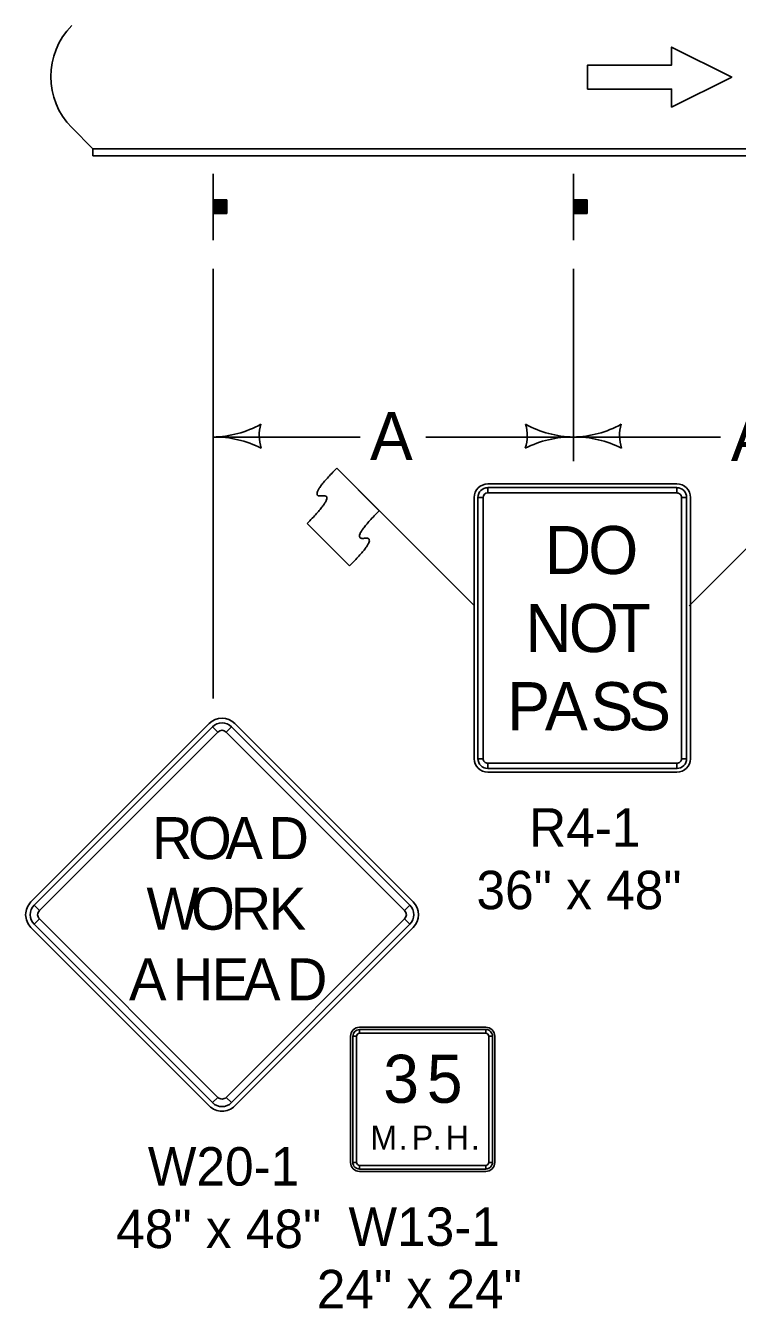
# Model space of a CAD drawing. Extents: x 10133 to 81668, y 4692 to 11018.
# Drawn here: x 20955 to 21251, y 6322 to 6856 of the extents above; entities that cross this region are included whole.
import ezdxf

# ---------------------------------------------------------------- set-up
doc = ezdxf.new("R2010")
doc.units = 0
for name, color, linetype in [('dsnCellElements', 7, 'Continuous'), ('dsnTextTabulation', 7, 'Continuous'), ('Level 5', 7, 'Continuous'), ('SheetAddendum', 7, 'Continuous')]:
    doc.layers.add(name, color=color, linetype=linetype)

msp = doc.modelspace()

# ---------------------------------------------------------------- linework, layer by layer
at = {"layer": 'dsnCellElements'}
for p, q in [((20982.53, 6804.8), (20973.74, 6813.59)), ((20973.74, 6813.59), (20982.53, 6804.8)), ((20982.53, 6801.8), (20982.53, 6804.8)), ((20982.53, 6804.8), (22482.53, 6804.8)), ((21032.53, 6794.3), (21032.53, 6766.8)), ((21182.53, 6794.3), (21182.53, 6766.8)), ((21032.94, 6777.86), (21032.94, 6783.44)), ((21033.22, 6783.44), (21033.22, 6777.86)), ((21033.48, 6777.86), (21033.48, 6783.44)), ((21033.75, 6783.44), (21033.75, 6777.86)), ((21033.97, 6777.86), (21033.97, 6783.44)), ((21034.18, 6783.44), (21034.18, 6777.86)), ((21034.52, 6777.86), (21034.52, 6783.44)), ((21034.78, 6783.44), (21034.78, 6777.86)), ((21035, 6777.86), (21034.98, 6783.44)), ((21035.32, 6783.44), (21035.32, 6777.86)), ((21035.7, 6777.86), (21035.7, 6783.44)), ((21036.13, 6783.44), (21036.13, 6777.86)), ((21036.35, 6777.86), (21036.33, 6783.44)), ((21036.77, 6783.44), (21036.78, 6777.86)), ((21036.99, 6777.86), (21036.99, 6783.44)), ((21037.31, 6783.44), (21037.31, 6777.86)), ((21037.53, 6777.86), (21037.53, 6783.44)), ((21037.85, 6783.44), (21037.85, 6777.86)), ((21182.94, 6777.86), (21182.94, 6783.44)), ((21183.22, 6783.44), (21183.22, 6777.86)), ((21183.48, 6777.86), (21183.48, 6783.44)), ((21183.75, 6783.44), (21183.75, 6777.86)), ((21183.97, 6777.86), (21183.97, 6783.44)), ((21184.18, 6783.44), (21184.18, 6777.86)), ((21184.52, 6777.86), (21184.52, 6783.44)), ((21184.78, 6783.44), (21184.78, 6777.86)), ((21185, 6777.86), (21184.98, 6783.44)), ((21185.32, 6783.44), (21185.32, 6777.86)), ((21185.7, 6777.86), (21185.7, 6783.44)), ((21186.13, 6783.44), (21186.13, 6777.86)), ((21186.35, 6777.86), (21186.33, 6783.44)), ((21186.77, 6783.44), (21186.78, 6777.86)), ((21186.99, 6777.86), (21186.99, 6783.44)), ((21187.31, 6783.44), (21187.31, 6777.86)), ((21187.53, 6777.86), (21187.53, 6783.44)), ((21187.85, 6783.44), (21187.85, 6777.86)), ((21032.53, 6575.99), (21032.53, 6754.8)), ((21182.53, 6674.8), (21182.53, 6754.8)), ((21032.53, 6684.8), (21093.7, 6684.8)), ((21121.03, 6684.8), (21182.53, 6684.8)), ((21182.53, 6684.8), (21243.7, 6684.8))]:
    msp.add_line(p, q, dxfattribs=at)
for points in [[(21188.42, 6839.63), (21188.42, 6829.63), (21223.42, 6829.63), (21223.42, 6822.13), (21248.42, 6834.63), (21223.42, 6847.13), (21223.42, 6839.63)], [(21032.62, 6777.86), (21032.62, 6783.48), (21038.25, 6783.48), (21038.25, 6777.86)], [(21182.62, 6777.86), (21182.62, 6783.48), (21188.25, 6783.48), (21188.25, 6777.86)]]:
    msp.add_lwpolyline(points, close=True, dxfattribs=at)
msp.add_lwpolyline([(21223.42, 6839.63), (21223.42, 6847.13), (21248.42, 6834.63), (21223.42, 6822.13), (21223.42, 6829.63), (21188.42, 6829.63), (21188.42, 6839.63), (21223.42, 6839.63)], dxfattribs=at)
for centre, radius, start, end in [((20994.95, 6834.8), 30, 135, 225), ((20994.95, 6834.8), 30, 135, 225), ((21031.77, 6727.3), 42.5, 271.0176, 299.0725), ((21068.14, 6685.43), 16.42, 163.2666, 198.7334), ((21146.91, 6685.43), 16.42, 341.2666, 16.7334), ((21183.28, 6727.3), 42.5, 240.9275, 268.9824), ((21181.77, 6727.3), 42.5, 271.0176, 299.0725), ((21218.14, 6685.43), 16.42, 163.2666, 198.7334), ((21033.26, 6642.31), 42.5, 62.9275, 90.9824), ((21181.8, 6642.31), 42.5, 89.0176, 117.0725), ((21183.26, 6642.31), 42.5, 62.9275, 90.9824)]:
    msp.add_arc(centre, radius, start, end, dxfattribs=at)
at = {"layer": 'dsnTextTabulation'}
for p, q in [((20982.53, 6804.8), (22482.53, 6804.8)), ((20982.53, 6804.8), (22482.53, 6804.8)), ((21627.53, 6804.8), (20982.53, 6804.8)), ((20982.53, 6804.8), (20982.53, 6801.8)), ((20982.53, 6801.8), (22482.53, 6801.8)), ((20982.53, 6801.8), (22482.53, 6801.8))]:
    msp.add_line(p, q, dxfattribs=at)
at = {"layer": 'Level 5'}
msp.add_line((21071.66, 6648.85), (21089.34, 6631.17), dxfattribs=at)
for points in [[(21084.03, 6671.84), (21071.66, 6659.45), (21084.03, 6661.22), (21071.66, 6648.85)], [(21101.72, 6654.16), (21089.34, 6641.78), (21101.71, 6643.55), (21089.34, 6631.17)]]:
    msp.add_open_spline(points, degree=2, dxfattribs=at)
at = {"layer": 'SheetAddendum'}
for p, q in [((21141.37, 6614.54), (21084.03, 6671.84)), ((21084.03, 6671.84), (21101.72, 6654.16)), ((21230.66, 6614.54), (21287.98, 6671.86)), ((21225.61, 6665.3), (21146.86, 6665.3)), ((21146.86, 6661.55), (21146.86, 6663.74)), ((21225.61, 6663.74), (21225.61, 6661.55)), ((21141.23, 6659.67), (21141.23, 6550.92)), ((21142.8, 6659.67), (21144.98, 6659.67)), ((21227.48, 6659.67), (21229.67, 6659.67)), ((21231.23, 6550.92), (21231.23, 6659.67)), ((21089.34, 6631.17), (21071.66, 6648.85)), ((21030.95, 6565.57), (20956.7, 6491.32)), ((21032.27, 6564.24), (21034.48, 6562.03)), ((21038.02, 6562.03), (21040.23, 6564.24)), ((21115.8, 6491.32), (21041.55, 6565.57)), ((21144.98, 6550.92), (21142.8, 6550.92)), ((21229.67, 6550.92), (21227.48, 6550.92)), ((21146.86, 6546.86), (21146.86, 6549.05)), ((21146.86, 6545.3), (21225.61, 6545.3)), ((21225.61, 6549.05), (21225.61, 6546.86)), ((20960.24, 6487.78), (20958.03, 6489.99)), ((21114.47, 6489.99), (21112.27, 6487.78)), ((20956.7, 6480.71), (21030.95, 6406.47)), ((20958.03, 6482.04), (20960.24, 6484.25)), ((21041.55, 6406.47), (21115.8, 6480.71)), ((21112.27, 6484.25), (21114.47, 6482.04)), ((21146.02, 6439.19), (21093.52, 6439.19)), ((21093.52, 6436.69), (21093.52, 6438.25)), ((21146.02, 6438.25), (21146.02, 6436.69)), ((21089.77, 6435.44), (21089.77, 6382.94)), ((21090.71, 6435.44), (21092.27, 6435.44)), ((21147.27, 6435.44), (21148.83, 6435.44)), ((21149.77, 6382.94), (21149.77, 6435.44)), ((21034.48, 6410), (21032.27, 6407.79)), ((21040.23, 6407.79), (21038.02, 6410)), ((21092.27, 6382.94), (21090.71, 6382.94)), ((21093.52, 6380.13), (21093.52, 6381.69)), ((21146.02, 6381.69), (21146.02, 6380.13)), ((21148.83, 6382.94), (21147.27, 6382.94)), ((21093.52, 6379.19), (21146.02, 6379.19))]:
    msp.add_line(p, q, dxfattribs=at)
for points in [[(21225.61, 6663.74), (21146.86, 6663.74), (21146.86, 6661.55), (21225.61, 6661.55), (21225.61, 6663.74)], [(21142.8, 6659.67), (21142.8, 6550.92), (21144.98, 6550.92), (21144.98, 6659.67), (21142.8, 6659.67)], [(21229.67, 6550.92), (21229.67, 6659.67), (21227.48, 6659.67), (21227.48, 6550.92), (21229.67, 6550.92)], [(21032.27, 6564.24), (20958.03, 6489.99), (20960.24, 6487.78), (21034.48, 6562.03), (21032.27, 6564.24)], [(21114.47, 6489.99), (21040.23, 6564.24), (21038.02, 6562.03), (21112.27, 6487.78), (21114.47, 6489.99)], [(21146.86, 6546.86), (21225.61, 6546.86), (21225.61, 6549.05), (21146.86, 6549.05), (21146.86, 6546.86)], [(20958.03, 6482.04), (21032.27, 6407.79), (21034.48, 6410), (20960.24, 6484.25), (20958.03, 6482.04)], [(21040.23, 6407.79), (21114.47, 6482.04), (21112.27, 6484.25), (21038.02, 6410), (21040.23, 6407.79)], [(21146.02, 6438.25), (21093.52, 6438.25), (21093.52, 6436.69), (21146.02, 6436.69), (21146.02, 6438.25)], [(21090.71, 6435.44), (21090.71, 6382.94), (21092.27, 6382.94), (21092.27, 6435.44), (21090.71, 6435.44)], [(21148.83, 6382.94), (21148.83, 6435.44), (21147.27, 6435.44), (21147.27, 6382.94), (21148.83, 6382.94)], [(21093.52, 6380.13), (21146.02, 6380.13), (21146.02, 6381.69), (21093.52, 6381.69), (21093.52, 6380.13)]]:
    msp.add_lwpolyline(points, close=True, dxfattribs=at)
for centre, radius, start, end in [((21146.86, 6659.67), 5.62, 90.0002, 179.9998), ((21146.86, 6659.67), 4.06, 90.0002, 179.9998), ((21225.61, 6659.67), 5.62, 0, 90.0002), ((21225.61, 6659.67), 4.06, 0, 90.0002), ((21146.86, 6659.67), 1.88, 90.0002, 179.9998), ((21225.61, 6659.67), 1.88, 0, 90.0002), ((21036.25, 6560.26), 7.5, 45, 134.9997), ((21036.25, 6560.26), 5.62, 45, 134.9997), ((21036.25, 6560.26), 2.5, 45, 134.9997), ((21146.86, 6550.92), 5.62, 179.9998, 270.0001), ((21146.86, 6550.92), 4.06, 179.9998, 270.0001), ((21146.86, 6550.92), 1.88, 179.9998, 270.0001), ((21225.61, 6550.92), 5.62, 270.0001, 0.0003), ((21225.61, 6550.92), 4.06, 270.0001, 0.0003), ((21225.61, 6550.92), 1.88, 270.0001, 0.0003), ((20962.01, 6486.02), 7.5, 134.9997, 225), ((20962.01, 6486.02), 5.62, 134.9997, 225), ((20962.01, 6486.02), 2.5, 134.9997, 225), ((21110.5, 6486.02), 2.5, 315.0002, 44.9998), ((21110.5, 6486.02), 5.62, 315.0002, 44.9998), ((21110.5, 6486.02), 7.5, 315.0002, 44.9998), ((21093.52, 6435.44), 3.75, 90.0002, 179.9998), ((21093.52, 6435.44), 2.81, 90.0002, 179.9998), ((21146.02, 6435.44), 3.75, 0, 90.0002), ((21146.02, 6435.44), 2.81, 0, 90.0002), ((21093.52, 6435.44), 1.25, 90.0002, 179.9998), ((21146.02, 6435.44), 1.25, 0, 90.0002), ((21036.25, 6411.77), 7.5, 225, 315.0002), ((21036.25, 6411.77), 5.62, 225, 315.0002), ((21036.25, 6411.77), 2.5, 225, 315.0002), ((21093.52, 6382.94), 3.75, 179.9998, 270.0001), ((21093.52, 6382.94), 2.81, 179.9998, 270.0001), ((21093.52, 6382.94), 1.25, 179.9998, 270.0001), ((21146.02, 6382.94), 3.75, 270.0001, 0.0003), ((21146.02, 6382.94), 2.81, 270.0001, 0.0003), ((21146.02, 6382.94), 1.25, 270.0001, 0.0003)]:
    msp.add_arc(centre, radius, start, end, dxfattribs=at)
for points in [[(21071.66, 6648.85), (21084.03, 6661.22), (21071.66, 6659.45), (21084.03, 6671.84)], [(21101.72, 6654.16), (21089.34, 6641.78), (21101.71, 6643.55), (21089.34, 6631.17)]]:
    msp.add_open_spline(points, degree=2, dxfattribs=at)

# ---------------------------------------------------------------- texts
at = {"layer": 'dsnCellElements'}
for p in [(21097.82, 6675.19), (21248.06, 6674.77)]:
    msp.add_text('A', height=20, dxfattribs=at).set_placement(p)
at = {"layer": 'SheetAddendum'}
for s, height, p in [('D', 20, (21170.61, 6627.8)), ('O', 20, (21188.73, 6627.8)), ('N', 20, (21162.48, 6595.3)), ('O', 20, (21180.61, 6595.3)), ('T', 20, (21198.42, 6595.3)), ('P', 20, (21154.97, 6562.8)), ('A', 20, (21170.66, 6562.8)), ('S', 20, (21189.62, 6562.8)), ('S', 20, (21205.31, 6562.8)), ('R4-1', 16, (21164.07, 6514.3)), ('R', 17.5, (21007.09, 6509.14)), ('O', 17.5, (21022.1, 6509.14)), ('A', 17.5, (21037.65, 6509.14)), ('D', 17.5, (21055.53, 6509.14)), ('36" x 48"', 16, (21142.17, 6488.3)), ('W', 17.5, (21004.8, 6479.77)), ('O', 17.5, (21023.4, 6479.77)), ('R', 17.5, (21039.81, 6479.77)), ('K', 17.5, (21055.67, 6479.77)), ('A', 17.5, (20997.53, 6450.39)), ('H', 17.5, (21015.73, 6450.39)), ('E', 17.5, (21031.96, 6450.39)), ('A', 17.5, (21045.01, 6450.39)), ('D', 17.5, (21063.22, 6450.39)), ('3', 20, (21103.38, 6407.73)), ('5', 20, (21121.51, 6407.73)), ('M', 10, (21098, 6388.25)), ('P', 10, (21115.25, 6388.25)), ('H', 10, (21129.37, 6388.25)), ('W20-1', 16, (21005.4, 6373.27)), ('.', 10, (21109.79, 6388.25)), ('.', 10, (21123.91, 6388.25)), ('.', 10, (21139.84, 6388.25)), ('48" x 48"', 16, (20992.19, 6347.27)), ('W13-1', 16, (21088.92, 6348.19)), ('24" x 24"', 16, (21075.71, 6322.19))]:
    msp.add_text(s, height=height, dxfattribs=at).set_placement(p)

doc.saveas('drawing.dxf')
